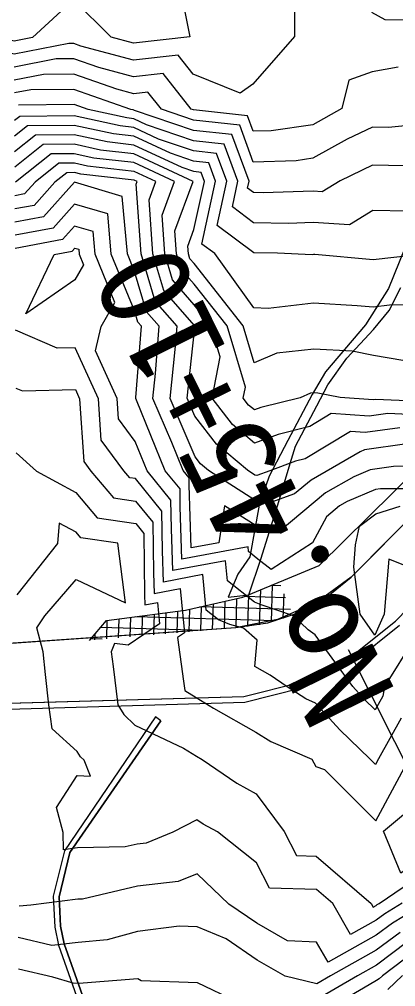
# Model space of a CAD drawing. Extents: x 42655 to 43811, y -141820 to -141156.
# Drawn here: x 43210.6 to 43242.7, y -141518.6 to -141436.2 of the extents above; entities that cross this region are included whole.
import ezdxf

# ---------------------------------------------------------------- set-up
doc = ezdxf.new("R2010")
doc.units = 0
for name, color, linetype in [('D-STR-HTXT', 7, 'Continuous'), ('ZE_HICN', 7, 'Continuous'), ('ZE_LWCN', 7, 'Continuous'), ('地形', 7, 'Continuous'), ('現況水路ﾊｯﾁ', 7, 'Continuous'), ('現況道路ﾊｯﾁ', 7, 'Continuous'), ('追加___', 7, 'Continuous'), ('追加____', 7, 'Continuous')]:
    doc.layers.add(name, color=color, linetype=linetype)

msp = doc.modelspace()

# ---------------------------------------------------------------- linework, layer by layer
at = {"layer": 'D-STR-HTXT'}
msp.add_line((43261.146, -141534.624), (43238.696, -141489.947), dxfattribs=at)
at = {"layer": 'ZE_HICN'}
for points in [[(43208.962, -141437.752), (43209.436, -141436.869), (43209.434, -141431.587), (43210.136, -141431.164), (43214.552, -141430.751), (43215.221, -141430.584), (43217.377, -141428.929), (43220.307, -141430.059), (43223.756, -141431.519), (43224.218, -141432.96), (43225.163, -141437.675), (43220.345, -141438.215), (43218.435, -141437.707), (43215.24, -141434.479), (43211.746, -141437.739), (43210.168, -141438.044), (43208.962, -141437.752)], [(43243.688, -141452.537), (43240.765, -141452.477), (43238.787, -141453.696), (43235.682, -141453.515), (43233.582, -141453.58), (43230.594, -141453.519), (43228.787, -141452.164), (43229.262, -141449.982), (43228.094, -141446.814), (43225.473, -141446.533), (43221.46, -141445.167), (43220.376, -141444.661), (43219.774, -141444.591), (43216.483, -141443.879), (43215.282, -141443.455), (43210.529, -141443.501)], [(43245.047, -141469.933), (43242.029, -141469.795), (43240.447, -141470.002), (43237.209, -141469.792), (43235.388, -141470.895), (43232.691, -141471.57), (43230.682, -141472.325), (43228.805, -141470.737), (43227.06, -141468.48), (43227.752, -141464.97), (43226.96, -141462.318), (43225.539, -141460.516), (43223.686, -141458.402), (43223.014, -141456.174), (43222.789, -141452.888), (43223.841, -141450.007), (43220.393, -141448.4), (43216.982, -141448.005), (43215.302, -141447.642), (43213.321, -141447.657), (43210.275, -141450.071)], [(43244.355, -141488.909), (43241.758, -141493.061), (43241.629, -141493.872), (43240.966, -141495.058), (43240.05, -141494.174), (43239.054, -141493.074), (43235.847, -141488.652), (43235.234, -141488.234), (43233.989, -141487.047), (43231.238, -141486.109), (43230.679, -141485.879), (43228.359, -141484.056), (43228.19, -141482.338), (43223.694, -141483.184), (43223.578, -141479.626), (43223.547, -141477.166), (43221.516, -141474.669), (43220.505, -141472.185), (43219.068, -141470.247), (43218.952, -141468.518), (43217.1, -141464.447), (43217.597, -141462.362), (43218.771, -141460.324), (43217.093, -141456.201), (43216.917, -141454.283), (43215.331, -141453.812), (43214.304, -141454.964), (43210.251, -141455.707)], [(43245.244, -141511.533), (43242.443, -141513.231), (43241.056, -141514.271), (43236.946, -141516.563), (43235.971, -141514.86), (43233.476, -141514.73), (43230.875, -141513.236), (43228.484, -141511.612), (43225.767, -141509.028), (43224.165, -141509.688), (43220.683, -141510.072), (43216.003, -141511.183), (43215.601, -141511.192), (43211.605, -141511.691), (43210.598, -141511.797)]]:
    msp.add_lwpolyline(points, dxfattribs=at)
at = {"layer": 'ZE_LWCN'}
for points in [[(43234.123, -141433.243), (43234.095, -141437.633), (43230.538, -141441.707), (43229.443, -141442.487), (43225.446, -141440.853), (43224.163, -141439.225), (43220.352, -141439.652), (43215.87, -141438.459), (43215.257, -141438.243), (43214.825, -141438.247), (43210.173, -141439.149), (43205.229, -141437.95), (43205.08, -141438.061), (43204.855, -141438.044), (43204.801, -141437.771), (43204.808, -141437.446), (43205.074, -141436.702), (43206.728, -141433.621)], [(43255.949, -141435.254), (43251.949, -141436.236), (43250.858, -141434.651), (43249.762, -141436.224), (43245.777, -141436.264), (43241.827, -141436.219), (43240.686, -141435.601)], [(43242.914, -141440.264), (43240.71, -141440.653), (43238.725, -141441.367), (43238.128, -141443.777), (43235.643, -141445.165), (43232.105, -141445.68), (43230.557, -141445.727), (43230.068, -141444.4), (43225.46, -141443.907), (43225.258, -141443.838), (43222.869, -141440.807), (43220.359, -141441.088), (43217.406, -141440.303), (43215.263, -141439.546), (43213.751, -141439.561), (43210.179, -141440.253)], [(43245.818, -141445.023), (43242.092, -141445.406), (43240.732, -141445.387), (43238.562, -141446.409), (43235.656, -141448.031), (43234.237, -141448.238), (43230.569, -141448.349), (43229.41, -141445.205), (43225.464, -141444.782), (43222.726, -141443.85), (43221.575, -141442.389), (43220.366, -141442.525), (43218.943, -141442.146), (43215.27, -141440.849), (43212.677, -141440.874), (43210.184, -141441.357)], [(43244.829, -141448.689), (43240.747, -141448.63), (43237.965, -141449.941), (43236.44, -141450.881), (43235.669, -141450.836), (43231.405, -141450.968), (43230.582, -141450.951), (43230.084, -141450.578), (43230.215, -141449.977), (43228.752, -141446.009), (43225.469, -141445.657), (43220.443, -141443.946), (43220.372, -141443.913), (43220.333, -141443.908), (43220.118, -141443.862), (43215.276, -141442.152), (43211.603, -141442.188), (43210.189, -141442.462)], [(43245.834, -141456.111), (43240.785, -141456.694), (43235.803, -141456.245), (43235.695, -141456.238), (43235.582, -141456.251), (43232.641, -141456.128), (43230.606, -141456.087), (43227.49, -141453.751), (43228.309, -141449.986), (43227.436, -141447.618), (43225.477, -141447.408), (43222.478, -141446.387), (43220.379, -141445.409), (43219.216, -141445.274), (43215.286, -141444.424), (43210.656, -141444.46), (43210.2, -141444.821)], [(43245.891, -141460.512), (43242.194, -141460.561), (43240.804, -141460.722), (43239.432, -141460.598), (43235.714, -141460.374), (43231.834, -141460.834), (43230.628, -141460.783), (43227.282, -141456.154), (43226.193, -141455.337), (43227.357, -141449.99), (43226.778, -141448.422), (43225.481, -141448.284), (43223.495, -141447.607), (43220.383, -141446.157), (43218.658, -141445.957), (43215.29, -141445.228), (43211.322, -141445.259), (43210.206, -141446.143)], [(43243.329, -141465.273), (43240.823, -141464.834), (43238.998, -141464.47), (43235.733, -141464.293), (43232.579, -141464.632), (43230.65, -141465.475), (43229.703, -141462.305), (43225.522, -141457.005), (43225.164, -141456.595), (43225.033, -141456.164), (43224.99, -141455.528), (43225.508, -141454.108), (43226.404, -141449.995), (43226.121, -141449.227), (43225.485, -141449.159), (43224.512, -141448.828), (43220.386, -141446.905), (43218.099, -141446.64), (43215.294, -141446.033), (43211.988, -141446.059), (43210.213, -141447.466)], [(43245.695, -141468.799), (43240.986, -141468.585), (43240.792, -141468.61), (43237.991, -141468.428), (43236.074, -141468.046), (43235.75, -141468.028), (43235.438, -141468.062), (43234.561, -141468.445), (43231.201, -141469.286), (43230.669, -141469.485), (43230.172, -141469.065), (43229.71, -141468.467), (43229.893, -141467.538), (43228.331, -141462.311), (43225.53, -141458.76), (43224.425, -141457.498), (43224.024, -141456.169), (43223.889, -141454.208), (43225.426, -141450), (43220.39, -141447.652), (43217.541, -141447.323), (43215.298, -141446.837), (43212.654, -141446.858), (43210.219, -141448.788)], [(43243.073, -141471.006), (43240.102, -141471.395), (43238.847, -141471.313), (43234.979, -141473.656), (43234.181, -141473.855), (43231.975, -141474.684), (43230.871, -141475.077), (43230.695, -141475.032), (43230.061, -141474.628), (43227.437, -141472.409), (43225.583, -141470.01), (43224.933, -141468.49), (43225.549, -141462.718), (43225.611, -141462.401), (43225.588, -141462.324), (43225.547, -141462.272), (43222.948, -141459.305), (43222.005, -141456.178), (43221.688, -141451.568), (43222.255, -141450.015), (43220.397, -141449.148), (43216.424, -141448.688), (43215.305, -141448.446), (43213.987, -141448.457), (43211.96, -141450.063), (43211.06, -141451.073), (43210.23, -141451.225)], [(43243.65, -141472.37), (43240.056, -141472.896), (43239.682, -141473.053), (43235.509, -141475.456), (43234.09, -141476.642), (43231.809, -141477.453), (43230.705, -141477.172), (43226.736, -141474.644), (43226.07, -141474.081), (43225.599, -141473.472), (43223.471, -141468.497), (43223.917, -141464.318), (43224.069, -141462.331), (43222.209, -141460.208), (43220.995, -141456.183), (43220.588, -141450.248), (43220.67, -141450.022), (43220.4, -141449.896), (43215.866, -141449.371), (43215.309, -141449.251), (43214.653, -141449.256), (43213.645, -141450.055), (43211.871, -141452.046), (43210.235, -141452.346)], [(43243.933, -141474.282), (43242.529, -141474.293), (43240.527, -141474.586), (43239.133, -141475.172), (43236.719, -141476.562), (43232.852, -141479.791), (43232.748, -141479.829), (43230.715, -141479.312), (43228.107, -141477.651), (43227.642, -141480.803), (43225.278, -141481.248), (43225.102, -141475.884), (43225.094, -141475.274), (43224.59, -141474.654), (43223.618, -141472.266), (43222.009, -141468.504), (43222.236, -141466.373), (43222.546, -141462.338), (43221.471, -141461.111), (43220.437, -141457.684), (43219.828, -141456.189), (43219.379, -141451.273), (43215.313, -141450.066), (43212.682, -141453.019), (43210.241, -141453.466)], [(43243.968, -141476.196), (43241.408, -141476.216), (43240.998, -141476.276), (43238.584, -141477.291), (43237.928, -141477.669), (43236.807, -141478.605), (43235.628, -141480.817), (43232.079, -141483.084), (43230.968, -141482.194), (43230.163, -141481.561), (43230.123, -141481.155), (43224.486, -141482.216), (43224.34, -141477.755), (43224.321, -141476.22), (43223.053, -141474.661), (43220.608, -141468.655), (43220.546, -141468.511), (43220.555, -141468.429), (43221.023, -141462.346), (43220.732, -141462.014), (43220.453, -141461.089), (43218.46, -141456.195), (43218.148, -141452.778), (43215.322, -141451.939), (43213.493, -141453.992), (43210.246, -141454.587)], [(43211.176, -141461.304), (43213.583, -141456.218), (43215.115, -141455.937), (43215.339, -141455.685), (43215.687, -141455.788), (43215.725, -141456.208), (43216.092, -141457.11), (43215.352, -141458.394), (43211.176, -141461.304)], [(43243.194, -141495.75), (43241.248, -141499.227), (43240.988, -141499.709), (43240.51, -141499.23), (43237.942, -141496.751), (43235.875, -141494.47), (43235.035, -141494.108), (43233.454, -141493.101), (43231.998, -141492.084), (43230.712, -141491.365), (43230.898, -141489.098), (43229.723, -141488.091), (43228.574, -141487.775), (43227.607, -141487.378), (43226.555, -141486.551), (43226.257, -141483.521), (43222.903, -141484.152), (43222.816, -141481.498), (43222.774, -141478.112), (43220.52, -141475.341), (43220.029, -141475.27), (43219.533, -141474.678), (43217.589, -141472.056), (43217.352, -141468.526), (43215.379, -141464.189), (43213.853, -141464.228), (43210.284, -141462.692)], [(43210.307, -141467.622), (43210.877, -141467.867), (43215.396, -141467.751), (43215.752, -141468.533), (43216.109, -141473.865), (43216.722, -141474.691), (43218.635, -141476.974), (43220.529, -141477.249), (43222, -141479.058), (43222.053, -141483.369), (43222.111, -141485.12), (43224.325, -141484.704), (43224.697, -141488.49), (43224.106, -141488.889), (43224.626, -141492.596), (43224.73, -141493.408), (43225.696, -141493.989), (43227.166, -141494.906), (43230.798, -141496.944), (43232.059, -141497.747), (43235.558, -141499.253), (43235.9, -141499.889), (43236.628, -141500.129), (43241.01, -141504.524), (43243.87, -141499.214)], [(43210.333, -141473.138), (43212.078, -141474.713), (43215.437, -141476.526), (43217.242, -141478.678), (43220.538, -141479.157), (43221.227, -141480.004), (43221.291, -141485.24), (43221.319, -141486.088), (43222.392, -141485.887), (43222.572, -141487.721), (43219.902, -141489.523), (43218.744, -141489.39), (43218.458, -141490.117), (43218.603, -141491.358), (43219.021, -141494.636), (43219.523, -141495.46), (43220.466, -141496.37), (43224.61, -141498.331), (43225.72, -141498.999), (43226.198, -141499.297), (43229.151, -141501.303), (43230.823, -141502.205), (43233.198, -141505.427), (43234.24, -141507.476), (43235.936, -141507.516), (43240.619, -141511.555), (43240.793, -141511.859), (43241.044, -141511.719), (43241.129, -141511.655), (43241.3, -141511.552), (43246.116, -141508.296)], [(43246.001, -141483.746), (43242.121, -141482.207), (43241.74, -141486.899), (43240.936, -141488.674), (43239.695, -141486.908), (43239.151, -141482.877), (43239.272, -141480.972), (43239.627, -141479.398), (43241.03, -141478.338), (43243.104, -141477.686)], [(43243.272, -141511.542), (43241.786, -141512.443), (43241.05, -141512.995), (43238.87, -141514.211), (43237.358, -141511.57), (43235.95, -141510.356), (43231.961, -141510.263), (43230.851, -141508.079), (43227.508, -141505.454), (43226.293, -141504.798), (43225.745, -141504.426), (43223.693, -141505.472), (43221.428, -141506.405), (43220.667, -141506.489), (43219.643, -141506.732), (43215.58, -141506.821), (43214.379, -141506.971), (43214.362, -141505.516), (43213.789, -141503.369), (43215.551, -141500.645), (43216.682, -141500.712), (43216.135, -141499.345), (43215.84, -141499.06), (43215.552, -141498.589), (43213.401, -141496.656), (43213.142, -141494.636), (43212.836, -141492.041), (43212.64, -141490.117), (43212.113, -141488.06), (43212.799, -141487.035), (43215.472, -141483.941), (43219.672, -141485.915), (43219.02, -141480.843), (43215.848, -141480.383), (43215.453, -141479.912), (43214.025, -141479.141), (43213.857, -141480.867), (43210.39, -141485.255)], [(43243.149, -141508.978), (43241.669, -141505.387), (43246.085, -141501.717), (43247.303, -141505.361), (43247.188, -141506.669), (43246.11, -141506.976), (43243.149, -141508.978)], [(43243.099, -141514.019), (43241.062, -141515.546), (43237.141, -141517.734), (43235.987, -141518.411), (43233.278, -141517.752), (43230.89, -141516.38), (43228.247, -141514.586), (43225.788, -141513.553), (43224.243, -141513.504), (43220.702, -141513.949), (43218.091, -141514.658), (43215.618, -141514.899), (43213.379, -141515.133), (43210.528, -141514.468)], [(43243.756, -141514.807), (43241.068, -141516.822), (43239.453, -141517.723), (43235.994, -141519.753)], [(43244.413, -141515.595), (43241.588, -141517.713), (43241.298, -141517.986), (43241.074, -141518.119), (43240.437, -141518.492), (43236, -141521.096)], [(43229.136, -141519.915), (43225.811, -141518.323), (43220.997, -141518.143), (43220.721, -141517.988), (43216.07, -141518.361), (43215.634, -141518.375), (43215.219, -141518.34), (43213.483, -141517.845), (43210.54, -141517.159)], [(43243.307, -141517.705), (43242.049, -141518.887)]]:
    msp.add_lwpolyline(points, dxfattribs=at)
at = {"layer": '地形'}
for points in [[(43243.487, -141455.685), (43242.095, -141459.132), (43240.124, -141462.221), (43236.722, -141466.244), (43235.601, -141468.174), (43233.513, -141472.084), (43231.929, -141475.134), (43231.077, -141477.614), (43230.266, -141482.016), (43229.261, -141483.483), (43228.429, -141485.441), (43230.185, -141485.243), (43231.252, -141482.122), (43232.749, -141477.294), (43233.702, -141474.056), (43234.178, -141472.56), (43235.983, -141469.121), (43236.935, -141467.353), (43238.536, -141465.068), (43240.816, -141462.62), (43242.144, -141461.016), (43243.164, -141459.044)], [(43222.238, -141495.642), (43214.454, -141507.066), (43213.512, -141510.935), (43213.636, -141513.564), (43213.964, -141515.124), (43215.651, -141519.939), (43216.35, -141523.02), (43216.309, -141524.786), (43214.459, -141531.12), (43211.745, -141540.29), (43210.264, -141545.68), (43208.537, -141549.254), (43206.194, -141553.904), (43205.166, -141558.381), (43204.014, -141563.487), (43203.973, -141566.495), (43203.069, -141569.206), (43201.712, -141572.656), (43201.341, -141575.375), (43200.273, -141579.318), (43200.067, -141581.947), (43200.562, -141585.203), (43200.809, -141587.257)], [(43222.688, -141495.995), (43214.935, -141507.204), (43214.015, -141510.983), (43214.133, -141513.5), (43214.447, -141514.99), (43216.132, -141519.801), (43216.851, -141522.969), (43216.807, -141524.863), (43214.939, -141531.261), (43212.226, -141540.427), (43210.734, -141545.857), (43208.986, -141549.475), (43206.668, -141554.075), (43205.654, -141558.492), (43204.514, -141563.546), (43204.472, -141566.58), (43203.539, -141569.377), (43202.2, -141572.783), (43201.832, -141575.475), (43200.767, -141579.404), (43200.57, -141581.929), (43201.057, -141585.136), (43201.305, -141587.197)]]:
    msp.add_lwpolyline(points, dxfattribs=at)
at = {"layer": '現況水路ﾊｯﾁ'}
for points in [[(43243.487, -141455.685), (43242.095, -141459.132), (43240.124, -141462.221), (43236.722, -141466.244), (43235.601, -141468.174), (43233.513, -141472.084), (43231.929, -141475.134), (43231.077, -141477.614), (43230.266, -141482.016), (43229.261, -141483.483), (43228.429, -141485.441), (43230.185, -141485.243), (43231.252, -141482.122), (43232.749, -141477.294), (43233.702, -141474.056), (43234.178, -141472.56), (43235.983, -141469.121), (43236.935, -141467.353), (43238.536, -141465.068), (43240.816, -141462.62), (43242.144, -141461.016), (43243.164, -141459.044)], [(43208.986, -141549.475), (43210.734, -141545.857), (43212.226, -141540.427), (43214.939, -141531.261), (43216.807, -141524.863), (43216.851, -141522.969), (43216.132, -141519.801), (43214.447, -141514.99), (43214.133, -141513.5), (43214.015, -141510.983), (43214.935, -141507.204), (43222.688, -141495.995), (43222.238, -141495.642), (43214.454, -141507.066), (43213.512, -141510.935), (43213.636, -141513.564), (43213.964, -141515.124), (43215.651, -141519.939), (43216.35, -141523.02), (43216.309, -141524.786), (43214.459, -141531.12), (43211.745, -141540.29), (43210.264, -141545.68)]]:
    msp.add_lwpolyline(points, dxfattribs=at)
at = {"layer": '現況道路ﾊｯﾁ'}
for points in [[(43262.378, -141460.105), (43262.378, -141460.105), (43238.919, -141483.749), (43238.919, -141483.749)], [(43242.696, -141487.482), (43242.696, -141487.482), (43242.725, -141487.453), (43265.902, -141463.653), (43265.902, -141463.653)], [(43238.919, -141483.749), (43235.973, -141485.905), (43232.626, -141487.361), (43229.041, -141488.045)], [(43229.768, -141493.908), (43234.506, -141492.712), (43238.882, -141490.537), (43242.696, -141487.482)], [(43229.041, -141488.045), (43229.041, -141488.045), (43206.773, -141489.581), (43206.773, -141489.581)], [(43206.636, -141494.579), (43206.636, -141494.579), (43229.768, -141493.908), (43229.768, -141493.908)]]:
    msp.add_lwpolyline(points, dxfattribs=at)
at = {"layer": '追加___'}
for p, q in [((43231.11, -141487.792), (43231.198, -141484.823)), ((43232.924, -141484.481), (43232.083, -141484.456)), ((43232.117, -141487.565), (43232.211, -141484.403)), ((43228.099, -141488.128), (43228.168, -141485.791)), ((43229.102, -141488.041), (43229.175, -141485.566)), ((43233.326, -141485.493), (43229.833, -141485.389)), ((43230.105, -141487.95), (43230.185, -141485.243)), ((43233.127, -141487.263), (43233.19, -141485.149)), ((43224.087, -141488.476), (43224.142, -141486.634)), ((43225.09, -141488.389), (43225.147, -141486.467)), ((43233.729, -141486.505), (43226.003, -141486.276)), ((43226.093, -141488.302), (43226.154, -141486.242)), ((43227.096, -141488.215), (43227.161, -141486.017)), ((43218.069, -141488.998), (43218.115, -141487.437)), ((43219.072, -141488.911), (43219.119, -141487.303)), ((43220.075, -141488.824), (43220.124, -141487.17)), ((43232.468, -141487.468), (43220.54, -141487.114)), ((43221.078, -141488.737), (43221.128, -141487.036)), ((43222.081, -141488.65), (43222.133, -141486.902)), ((43223.084, -141488.563), (43223.137, -141486.768)), ((43226.284, -141488.285), (43217.538, -141488.025)), ((43217.691, -141489.03), (43216.7, -141489.001)), ((43217.066, -141489.085), (43217.081, -141488.557))]:
    msp.add_line(p, q, dxfattribs=at)
at = {"layer": '追加____'}
for p, q in [((43236.191, -141482.752), (43263.937, -141455.283)), ((43262.378, -141460.105), (43238.919, -141483.749)), ((43229.679, -141485.453), (43236.191, -141482.752)), ((43224.782, -141486.549), (43229.679, -141485.453)), ((43218.035, -141487.448), (43224.782, -141486.549)), ((43216.593, -141489.126), (43218.035, -141487.448)), ((43206.773, -141489.581), (43229.088, -141488.042)), ((43206.636, -141494.579), (43229.768, -141493.908)), ((43206.619, -141495.079), (43229.838, -141494.403))]:
    msp.add_line(p, q, dxfattribs=at)
for points in [[(43229.088, -141488.042), (43231.795, -141487.645), (43234.389, -141486.777), (43236.788, -141485.465), (43238.919, -141483.749)], [(43229.768, -141493.908), (43234.506, -141492.712), (43238.882, -141490.537), (43242.696, -141487.482)], [(43229.838, -141494.403), (43234.679, -141493.181), (43239.151, -141490.958), (43243.049, -141487.837)]]:
    msp.add_lwpolyline(points, dxfattribs=at)

# ---------------------------------------------------------------- texts
at = {"layer": 'D-STR-HTXT'}
msp.add_text('No.45+10', height=7.9662, rotation=116.25562, dxfattribs=at).set_placement((43242.812, -141493.65))

doc.saveas('drawing.dxf')
